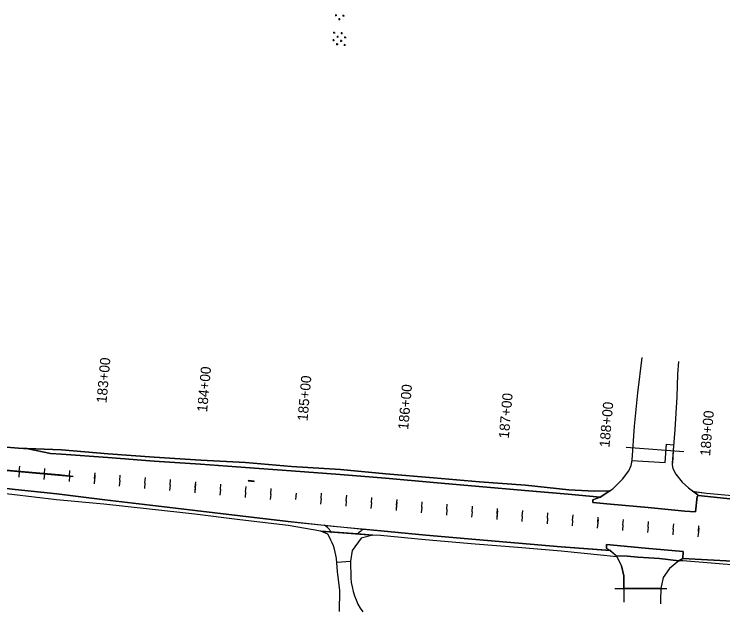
# Model space of a CAD drawing. Extents: x 20499880 to 20505309, y 7953507 to 7955507.
# Drawn here: x 20501928 to 20502629, y 7953741 to 7954332 of the extents above; entities that cross this region are included whole.
import ezdxf

# ---------------------------------------------------------------- set-up
doc = ezdxf.new("R2010")
doc.units = 0
for name, color, linetype in [('Alignment', 7, 'Continuous'), ('Curb', 7, 'Continuous'), ('Draft_0', 7, 'Continuous'), ('Entrance', 7, 'Continuous')]:
    doc.layers.add(name, color=color, linetype=linetype)

msp = doc.modelspace()

# ---------------------------------------------------------------- linework, layer by layer
at = {"layer": 'Alignment'}
for p, q in [((20502007.59, 7953872.88), (20502008.07, 7953878.32)), ((20502007.59, 7953872.88), (20502007.1, 7953867.44)), ((20502107.19, 7953863.96), (20502106.7, 7953858.52)), ((20502107.19, 7953863.96), (20502107.67, 7953869.4)), ((20502207.06, 7953858.1), (20502206.52, 7953852.01)), ((20502207.06, 7953858.1), (20502206.52, 7953852.01)), ((20502306.41, 7953846.39), (20502306.89, 7953851.82)), ((20502306.41, 7953846.39), (20502305.94, 7953840.95)), ((20502406.04, 7953837.72), (20502406.51, 7953843.16)), ((20502406.04, 7953837.72), (20502405.56, 7953832.28)), ((20502505.66, 7953829.05), (20502505.19, 7953823.61)), ((20502505.66, 7953829.05), (20502506.13, 7953834.49)), ((20502605.28, 7953820.38), (20502605.76, 7953825.82)), ((20502605.28, 7953820.38), (20502604.81, 7953814.94))]:
    msp.add_line(p, q, dxfattribs=at)
at = {"layer": 'Curb'}
for p, q in [((20502245.56, 7954331.6), (20502247.37, 7954331.45)), ((20502246.39, 7954330.61), (20502246.46, 7954331.52)), ((20502246.46, 7954331.52), (20502246.54, 7954332.44)), ((20502248.98, 7954327.54), (20502250.79, 7954327.39)), ((20502249.81, 7954326.55), (20502249.88, 7954327.47)), ((20502249.88, 7954327.47), (20502249.96, 7954328.38)), ((20502253.04, 7954331), (20502254.85, 7954330.86)), ((20502253.64, 7954327.17), (20502253.64, 7954327.17)), ((20502253.87, 7954330.01), (20502253.94, 7954330.93)), ((20502253.94, 7954330.93), (20502254.02, 7954331.85)), ((20502243.81, 7954314.25), (20502245.62, 7954314.1)), ((20502244.64, 7954313.26), (20502244.72, 7954314.17)), ((20502244.72, 7954314.17), (20502244.79, 7954315.09)), ((20502251.29, 7954313.65), (20502253.1, 7954313.51)), ((20502252.12, 7954312.66), (20502252.19, 7954313.58)), ((20502252.19, 7954313.58), (20502252.27, 7954314.5)), ((20502243.21, 7954306.76), (20502245.03, 7954306.62)), ((20502244.05, 7954305.77), (20502244.12, 7954306.69)), ((20502244.12, 7954306.69), (20502244.19, 7954307.61)), ((20502247.27, 7954310.23), (20502249.09, 7954310.08)), ((20502248.11, 7954309.24), (20502248.18, 7954310.16)), ((20502248.18, 7954310.16), (20502248.25, 7954311.07)), ((20502250.69, 7954306.17), (20502252.51, 7954306.02)), ((20502251.53, 7954305.18), (20502251.6, 7954306.1)), ((20502251.6, 7954306.1), (20502251.67, 7954307.02)), ((20502254.75, 7954309.63), (20502256.57, 7954309.49)), ((20502255.59, 7954308.64), (20502255.66, 7954309.56)), ((20502255.66, 7954309.56), (20502255.73, 7954310.48)), ((20502246.68, 7954302.74), (20502248.49, 7954302.6)), ((20502247.51, 7954301.75), (20502247.59, 7954302.67)), ((20502247.59, 7954302.67), (20502247.66, 7954303.59)), ((20502254.16, 7954302.15), (20502255.97, 7954302.01)), ((20502254.99, 7954301.16), (20502255.07, 7954302.08)), ((20502255.07, 7954302.08), (20502255.14, 7954303)), ((20502255.9, 7954301.09), (20502255.9, 7954301.09)), ((20502533.8, 7953903.62), (20502590.78, 7953899.62)), ((20502238.51, 7953817.52), (20502231.62, 7953820.75)), ((20502231.62, 7953820.75), (20502282.87, 7953816.6)), ((20502282.87, 7953816.6), (20502271.33, 7953813.72)), ((20502271.33, 7953813.72), (20502262.49, 7953801.57)), ((20502262.49, 7953801.57), (20502260.96, 7953791.08)), ((20502248.15, 7953780.75), (20502247.03, 7953793.58)), ((20502247.35, 7953789.89), (20502260.96, 7953791.08)), ((20502260.96, 7953791.08), (20502261.29, 7953774.37)), ((20502250.3, 7953761.99), (20502248.15, 7953780.75)), ((20502249.87, 7953741.24), (20502250.3, 7953761.99)), ((20502522.58, 7953763.94), (20502573.97, 7953764))]:
    msp.add_line(p, q, dxfattribs=at)
for points in [[(20502538.6, 7953885.61), (20502538.97, 7953887.28), (20502539.53, 7953890.87), (20502541.89, 7953924.41), (20502545.25, 7953957.47), (20502549.51, 7953992.51)], [(20502585.53, 7953988.6), (20502584.41, 7953976.07), (20502584.12, 7953964.43), (20502583.77, 7953953.66), (20502581.79, 7953921.39), (20502579.33, 7953888.04), (20502579.42, 7953886.25), (20502580, 7953882.75)], [(20502508.71, 7953854.1), (20502476.24, 7953857.13), (20502433.37, 7953860.92), (20502388.38, 7953864.8), (20502343.12, 7953868.7), (20502295.63, 7953872.96), (20502250.52, 7953876.88), (20502202.15, 7953880.25), (20502156.92, 7953883.71), (20502112.34, 7953886.91), (20502066.45, 7953889.96), (20502020.52, 7953893.42), (20501974.76, 7953896.96), (20501963.75, 7953897.64), (20501941.91, 7953902.08), (20501932.22, 7953902.73), (20501888.64, 7953906.43), (20501845.21, 7953910.05), (20501800.31, 7953913.93), (20501792.88, 7953915.17), (20501784.48, 7953916.66), (20501777.79, 7953918.36), (20501775.73, 7953916.88)], [(20502518.56, 7953860.52), (20502502.35, 7953860.33), (20502476.86, 7953861.5), (20502434.01, 7953866.03), (20502388.67, 7953869.42), (20502343.15, 7953873.38), (20502295.77, 7953877.43), (20502250.81, 7953881.72), (20502202.45, 7953884.66), (20502156.79, 7953888.46), (20502112.72, 7953891.07), (20502066.67, 7953894.04), (20502021.12, 7953897.12), (20501974.88, 7953901.25), (20501932.36, 7953902.9), (20501932.22, 7953902.73)], [(20502604.73, 7953856.51), (20502604.91, 7953856.41), (20502604.87, 7953855.94), (20502603.89, 7953854.91), (20502602.32, 7953839.62), (20502591.71, 7953840.55), (20502555.56, 7953843.93), (20502518.28, 7953847.24), (20502500.68, 7953848.85), (20502500.9, 7953851.52), (20502507.9, 7953854.14), (20502520.65, 7953862.43), (20502530.09, 7953871.98), (20502536.37, 7953880.41), (20502538.6, 7953885.61)], [(20502580, 7953882.75), (20502582.94, 7953876.91), (20502589.32, 7953869.01), (20502595.38, 7953863.36), (20502604.73, 7953856.51)], [(20502231.62, 7953820.75), (20502199.17, 7953826.29), (20502151.45, 7953831.89), (20502106.7, 7953837.39), (20502061.97, 7953842.24), (20502016.61, 7953847.32), (20501969.72, 7953851.76), (20501925.5, 7953856.87), (20501885.2, 7953860.84), (20501842.43, 7953864.72), (20501797.59, 7953869.19), (20501781.93, 7953870.67)], [(20502518.54, 7953801.39), (20502469.5, 7953805.15), (20502427.01, 7953808.84), (20502384.97, 7953812.36), (20502335.32, 7953816.81), (20502290.75, 7953820.83), (20502257.86, 7953823.97), (20502243.8, 7953825.24), (20502199.03, 7953830.21), (20502151.73, 7953835.86), (20502107.06, 7953841.12), (20502062.39, 7953846.41), (20502017.6, 7953851.77), (20501970.15, 7953857.55), (20501929.07, 7953862.02), (20501885.51, 7953866.8), (20501842, 7953870.66), (20501797.75, 7953874.36), (20501788.26, 7953875.08)], [(20502599.22, 7953860.08), (20502613.41, 7953858.2), (20502624.25, 7953857.16), (20502638.67, 7953856.01), (20502686.81, 7953850.53), (20502727.71, 7953845.97), (20502768.95, 7953842.37), (20502821.23, 7953837.04), (20502870.55, 7953832.33), (20502915.37, 7953828.48), (20502964.09, 7953822.56), (20503011.13, 7953817.59)], [(20502683.66, 7953847.72), (20502604.97, 7953855.85), (20502604.87, 7953855.94)], [(20502524.18, 7953795.13), (20502511.59, 7953796.53), (20502469.49, 7953800.93), (20502426.39, 7953804.45), (20502384.32, 7953807.74), (20502334.71, 7953812.11), (20502290.7, 7953816.17), (20502282.87, 7953816.6)], [(20502514.07, 7953803.75), (20502518.19, 7953801.33), (20502524.13, 7953796.22), (20502529.21, 7953786.24), (20502531.38, 7953776.25), (20502531.37, 7953764.74), (20502531.41, 7953752.67), (20502531.44, 7953750.28)], [(20502589.73, 7953793.5), (20502590.13, 7953800.59), (20502552.49, 7953803.94), (20502514.26, 7953807.27), (20502514.15, 7953803.58)], [(20502589.73, 7953793.5), (20502589.7, 7953793.43), (20502585.88, 7953791.21), (20502576.77, 7953783.76), (20502570.27, 7953774.61), (20502567.99, 7953764), (20502567.81, 7953752.08), (20502567.64, 7953748.54)], [(20503203, 7953746.48), (20503187.43, 7953748.31), (20503148.01, 7953751.45), (20503102.07, 7953755.64), (20503052.65, 7953759.66), (20503007.95, 7953762.75), (20502958.36, 7953766.12), (20502913.6, 7953768.86), (20502894.96, 7953770.99), (20502884.48, 7953774.86), (20502881.33, 7953776.1), (20502878.6, 7953776.38), (20502864.38, 7953777.26), (20502819.32, 7953780.07), (20502768.91, 7953783.31), (20502724.32, 7953785.92), (20502678.25, 7953788.48), (20502632.89, 7953791.29), (20502589.73, 7953793.5)], [(20502894.96, 7953770.99), (20502894.83, 7953770.82), (20502864.19, 7953772), (20502819.04, 7953774.42), (20502677.96, 7953783.92), (20502589.95, 7953791.14), (20502585.88, 7953791.21)]]:
    msp.add_lwpolyline(points, dxfattribs=at)
msp.add_arc((20502220.84, 7953806.15), 25, 30.58153, 55.07977, dxfattribs=at)
for centre, major_axis, ratio, start_param, end_param in [((20502179.6, 7953782.69), (4.76, 68.6), 0.992943, 4.940145, 5.312217), ((20502324.6, 7953777.78), (-44.62, -45.27), 0.994164, 5.541449, 6.111171)]:
    msp.add_ellipse(centre, major_axis=major_axis, ratio=ratio, start_param=start_param, end_param=end_param, dxfattribs=at)
at = {"layer": 'Draft_0'}
for points in [[(20501888.64, 7953906.43), (20501932.22, 7953902.73), (20501941.91, 7953902.08), (20501963.75, 7953897.64), (20501974.76, 7953896.96), (20502020.52, 7953893.42), (20502066.45, 7953889.96), (20502112.34, 7953886.91), (20502156.92, 7953883.71), (20502202.15, 7953880.25), (20502250.52, 7953876.88), (20502295.63, 7953872.96), (20502343.12, 7953868.7), (20502388.38, 7953864.8), (20502433.37, 7953860.92), (20502476.24, 7953857.13), (20502507.95, 7953854.17), (20502507.9, 7953854.14), (20502500.9, 7953851.52), (20502500.68, 7953848.85), (20502518.28, 7953847.24), (20502555.56, 7953843.93), (20502591.71, 7953840.55), (20502602.32, 7953839.62), (20502603.89, 7953854.91), (20502604.87, 7953855.94), (20502604.97, 7953855.85), (20502683.66, 7953847.72)], [(20502632.89, 7953791.29), (20502589.73, 7953793.5), (20502590.13, 7953800.59), (20502552.49, 7953803.94), (20502514.26, 7953807.27), (20502514.15, 7953803.71), (20502514.26, 7953807.27), (20502552.49, 7953803.94), (20502590.13, 7953800.59), (20502589.73, 7953793.5), (20502589.7, 7953793.43), (20502585.88, 7953791.21), (20502566.8, 7953793.49), (20502556.1, 7953794.2), (20502545.42, 7953795.02), (20502535.02, 7953795.72), (20502524.13, 7953796.22), (20502518.19, 7953801.33), (20502518.03, 7953801.42), (20502469.5, 7953805.15), (20502427.01, 7953808.84), (20502384.97, 7953812.36), (20502335.32, 7953816.81), (20502290.75, 7953820.83), (20502257.86, 7953823.97), (20502243.8, 7953825.24), (20502199.03, 7953830.21), (20502151.73, 7953835.86), (20502107.06, 7953841.12), (20502062.39, 7953846.41), (20502017.6, 7953851.77), (20501970.15, 7953857.55), (20501929.07, 7953862.02), (20501885.51, 7953866.8)], [(20501885.51, 7953866.8), (20501929.07, 7953862.02), (20501970.15, 7953857.55), (20502017.6, 7953851.77), (20502062.39, 7953846.41), (20502107.06, 7953841.12), (20502151.73, 7953835.86), (20502199.03, 7953830.21), (20502273.82, 7953822.45)], [(20502267.76, 7953817.82), (20502231.62, 7953820.75), (20502199.17, 7953826.29), (20502151.45, 7953831.89), (20502106.7, 7953837.39), (20502061.97, 7953842.24), (20502016.61, 7953847.32), (20501969.72, 7953851.76), (20501925.5, 7953856.87)], [(20502683.66, 7953847.72), (20502604.97, 7953855.85), (20502604.87, 7953855.94), (20502604.91, 7953856.41), (20502604.73, 7953856.51), (20502599.99, 7953859.98), (20502613.41, 7953858.2), (20502624.25, 7953857.16), (20502638.67, 7953856.01)], [(20502273.82, 7953822.45), (20502290.75, 7953820.83), (20502335.32, 7953816.81), (20502384.97, 7953812.36), (20502427.01, 7953808.84), (20502469.5, 7953805.15), (20502518.03, 7953801.42), (20502524.13, 7953796.22), (20502524.18, 7953795.13), (20502511.59, 7953796.53), (20502469.49, 7953800.93), (20502426.39, 7953804.45), (20502384.32, 7953807.74), (20502334.71, 7953812.11), (20502290.7, 7953816.17), (20502282.87, 7953816.6), (20502267.76, 7953817.82)]]:
    msp.add_lwpolyline(points, dxfattribs=at)
for points in [[(20502589.32, 7953869.01), (20502595.38, 7953863.36), (20502604.73, 7953856.51), (20502604.91, 7953856.41), (20502604.87, 7953855.94), (20502603.89, 7953854.91), (20502602.32, 7953839.62), (20502591.71, 7953840.55), (20502555.56, 7953843.93), (20502518.28, 7953847.24), (20502500.68, 7953848.85), (20502500.9, 7953851.52), (20502507.9, 7953854.14), (20502520.65, 7953862.43), (20502530.09, 7953871.98), (20502536.37, 7953880.41), (20502538.6, 7953885.61), (20502538.97, 7953887.28), (20502539.53, 7953890.87), (20502539.39, 7953890.66), (20502572.28, 7953888.46), (20502573.71, 7953906.78), (20502580.67, 7953906.24), (20502579.49, 7953887.98), (20502579.33, 7953888.04), (20502579.42, 7953886.25), (20502580, 7953882.75), (20502582.94, 7953876.91)], [(20501930.43, 7953880.17), (20501886.79, 7953883.97), (20501843.25, 7953887.96), (20501798.99, 7953891.99), (20501776.24, 7953894.08), (20501756.69, 7953895.8), (20501737.84, 7953897.58), (20501719.76, 7953899.02), (20501719.32, 7953899.06), (20501719.29, 7953898.7), (20501986.35, 7953874.78), (20501972.35, 7953876.5)], [(20502507.95, 7953854.17), (20502476.24, 7953857.13), (20502433.37, 7953860.92), (20502388.38, 7953864.8), (20502343.12, 7953868.7), (20502295.63, 7953872.96), (20502250.52, 7953876.88), (20502202.15, 7953880.25), (20502156.92, 7953883.71), (20502112.34, 7953886.91), (20502066.45, 7953889.96), (20502020.52, 7953893.42), (20501974.76, 7953896.96), (20501963.75, 7953897.64), (20501941.91, 7953902.08), (20501932.22, 7953902.73), (20501932.36, 7953902.9), (20501974.88, 7953901.25), (20502021.12, 7953897.12), (20502066.67, 7953894.04), (20502112.72, 7953891.07), (20502156.79, 7953888.46), (20502202.45, 7953884.66), (20502250.81, 7953881.72), (20502295.77, 7953877.43), (20502343.15, 7953873.38), (20502388.67, 7953869.42), (20502434.01, 7953866.03), (20502476.86, 7953861.5), (20502502.35, 7953860.33), (20502517.7, 7953860.51)], [(20502165.54, 7953870.25), (20502159.73, 7953870.66), (20502159.72, 7953870.32), (20502165.52, 7953869.82)], [(20502531.37, 7953763.95), (20502531.37, 7953764.74), (20502531.38, 7953776.25), (20502529.21, 7953786.24), (20502524.13, 7953796.22), (20502535.02, 7953795.72), (20502545.42, 7953795.02), (20502556.1, 7953794.2), (20502566.8, 7953793.49), (20502585.88, 7953791.21), (20502576.77, 7953783.76), (20502570.27, 7953774.61), (20502567.99, 7953764)], [(20502677.96, 7953783.92), (20502589.95, 7953791.14), (20502585.88, 7953791.21), (20502589.7, 7953793.43), (20502589.73, 7953793.5), (20502632.89, 7953791.29), (20502678.25, 7953788.48), (20502724.32, 7953785.92), (20502768.91, 7953783.31), (20502819.32, 7953780.07), (20502864.38, 7953777.26), (20502878.6, 7953776.38), (20502881.33, 7953776.1), (20502884.48, 7953774.86), (20502894.96, 7953770.99), (20502894.83, 7953770.82), (20502864.19, 7953772), (20502819.04, 7953774.42)]]:
    msp.add_lwpolyline(points, close=True, dxfattribs=at)
for centre, radius, start, end in [((20502285.78, 7953800.49), 25, 118.58239, 136.11846), ((20502286.12, 7953800.05), 25.55, 118.773, 135.92785)]:
    msp.add_arc(centre, radius, start, end, dxfattribs=at)
at = {"layer": 'Entrance'}
for p, q in [((20501932.88, 7953879.57), (20501933.37, 7953885.01)), ((20501932.88, 7953879.57), (20501932.4, 7953874.13)), ((20501957.79, 7953877.34), (20501958.27, 7953882.78)), ((20501982.69, 7953875.11), (20501983.17, 7953880.55)), ((20501957.79, 7953877.34), (20501957.3, 7953871.9)), ((20501982.69, 7953875.11), (20501982.2, 7953869.67)), ((20502007.86, 7953875.93), (20502007.31, 7953869.83)), ((20502007.86, 7953875.93), (20502007.31, 7953869.83)), ((20502032.49, 7953870.65), (20502032, 7953865.21)), ((20502032.49, 7953870.65), (20502032.97, 7953876.09)), ((20502057.39, 7953868.42), (20502057.87, 7953873.86)), ((20502082.29, 7953866.19), (20502082.77, 7953871.63)), ((20502057.39, 7953868.42), (20502056.9, 7953862.98)), ((20502082.29, 7953866.19), (20502081.8, 7953860.75)), ((20502107.46, 7953867.01), (20502106.91, 7953860.92)), ((20502107.46, 7953867.01), (20502106.91, 7953860.92)), ((20502132.09, 7953861.73), (20502132.57, 7953867.17)), ((20502156.99, 7953859.5), (20502157.48, 7953864.94)), ((20502132.09, 7953861.73), (20502131.6, 7953856.3)), ((20502156.99, 7953859.5), (20502156.5, 7953854.07)), ((20502181.89, 7953857.27), (20502181.4, 7953851.84)), ((20502181.89, 7953857.27), (20502182.38, 7953862.71)), ((20502207.06, 7953858.1), (20502206.52, 7953852.01)), ((20502207.06, 7953858.1), (20502206.52, 7953852.01)), ((20502231.7, 7953852.89), (20502232.17, 7953858.33)), ((20502231.7, 7953852.89), (20502231.22, 7953847.45)), ((20502256.6, 7953850.72), (20502256.13, 7953845.28)), ((20502256.6, 7953850.72), (20502257.08, 7953856.16)), ((20502281.51, 7953848.55), (20502281.98, 7953853.99)), ((20502331.32, 7953844.22), (20502331.79, 7953849.66)), ((20502281.51, 7953848.55), (20502281.03, 7953843.11)), ((20502306.68, 7953849.43), (20502306.15, 7953843.34)), ((20502306.68, 7953849.43), (20502306.15, 7953843.34)), ((20502331.32, 7953844.22), (20502330.85, 7953838.78)), ((20502356.23, 7953842.05), (20502356.7, 7953847.49)), ((20502381.13, 7953839.88), (20502381.6, 7953845.32)), ((20502356.23, 7953842.05), (20502355.75, 7953836.61)), ((20502381.13, 7953839.88), (20502380.66, 7953834.44)), ((20502406.3, 7953840.76), (20502405.77, 7953834.67)), ((20502406.3, 7953840.76), (20502405.77, 7953834.67)), ((20502430.94, 7953835.55), (20502430.47, 7953830.11)), ((20502430.94, 7953835.55), (20502431.42, 7953840.99)), ((20502455.85, 7953833.38), (20502456.32, 7953838.82)), ((20502480.75, 7953831.21), (20502481.23, 7953836.65)), ((20502455.85, 7953833.38), (20502455.38, 7953827.94)), ((20502480.75, 7953831.21), (20502480.28, 7953825.77)), ((20502505.93, 7953832.09), (20502505.4, 7953826)), ((20502505.93, 7953832.09), (20502505.4, 7953826)), ((20502530.57, 7953826.88), (20502531.04, 7953832.32)), ((20502555.47, 7953824.71), (20502555.95, 7953830.15)), ((20502530.57, 7953826.88), (20502530.09, 7953821.44)), ((20502555.47, 7953824.71), (20502555, 7953819.27)), ((20502580.38, 7953822.54), (20502579.9, 7953817.1)), ((20502580.38, 7953822.54), (20502580.85, 7953827.98)), ((20502605.55, 7953823.43), (20502605.02, 7953817.33)), ((20502605.55, 7953823.43), (20502605.02, 7953817.33))]:
    msp.add_line(p, q, dxfattribs=at)

# ---------------------------------------------------------------- texts
at = {"layer": 'Alignment'}
msp.add_text('185+00', height=10.02, rotation=85.02642, dxfattribs=at).set_placement((20502218.28, 7953929.34))
at = {"layer": 'Entrance'}
for s, rotation, p in [('183+00', 84.88337, (20502019.26, 7953947.14)), ('184+00', 84.88337, (20502118.87, 7953938.22)), ('185+00', 85.02642, (20502218.28, 7953929.34)), ('186+00', 85.02642, (20502317.91, 7953920.67)), ('187+00', 85.02642, (20502417.53, 7953912)), ('188+00', 85.02642, (20502517.15, 7953903.33)), ('189+00', 85.02642, (20502616.78, 7953894.66))]:
    msp.add_text(s, height=10.02, rotation=rotation, dxfattribs=at).set_placement(p)

doc.saveas('drawing.dxf')
